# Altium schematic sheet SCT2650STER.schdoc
size 127 x 101 mm
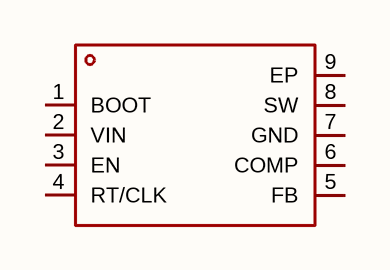
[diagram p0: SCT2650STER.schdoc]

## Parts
U?  sct2650ster  [ESOP-8_L4.9-W3.9-P1.27-LS6.0-BL-EP-2]  (value not drawn)

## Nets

Not connected (* = marked no-connect by the designer): U? 1(BOOT) 2(VIN) 3(EN) 4(RT/CLK) 5(FB) 6(COMP) 7(GND) 8(SW) 9(EP)

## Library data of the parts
U? = sct2650ster: 功能类型:降压型;工作电压:4.5V~60V;输出电压:800mV~57V;输出电流:5A;输出类型:可调;; Manufacturer: SCT(芯洲科技); AddInBom: yes; ModelId: 0078439d9e964752ad4b3f828dcb5664; ModelTransform: 192.913,236.22,0,0,0,0,0,0,0; Function: 降压型; Output Current: 5A; Frequency - Switching: 100kHz~1.2MHz; Synchronous Rectifier: 否; Number of Outputs: 1; Topology: 降压式; Quiescent Current: 175uA; Switch tube (built-in/external): 内置; Output Type: 可调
